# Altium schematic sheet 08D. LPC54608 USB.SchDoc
size A4; CheckedBy: 赵金生; Author: 伍伟业; CompanyName: 广州周立功单片机科技有限公司; DocumentNumber: 11; SheetNumber: 8D; SheetTotal: 19; PageSetup: Record=PageOptions|CenterHorizontal=True|CenterVertical=True|PrintScale=1.00|XCorrection=1.00|YCorrection=1.00|PrintKind=0|BorderSize=5000000|LeftOffset=0|BottomOffset=0|Orientation=2|PaperLength=1000|PaperWidth=1000|Scale=100|PaperSource=7|PrintQuality=600|MediaType=1|DitherType=10|PaperKind=A4|PrintScaleMode=1; DesignDate: 2017-3-16; CheckDate: 2017-3-16; SheetName: LPC54608 USB; SheetVersion: V1.00; SheetDescription: LPC54608的USB总线
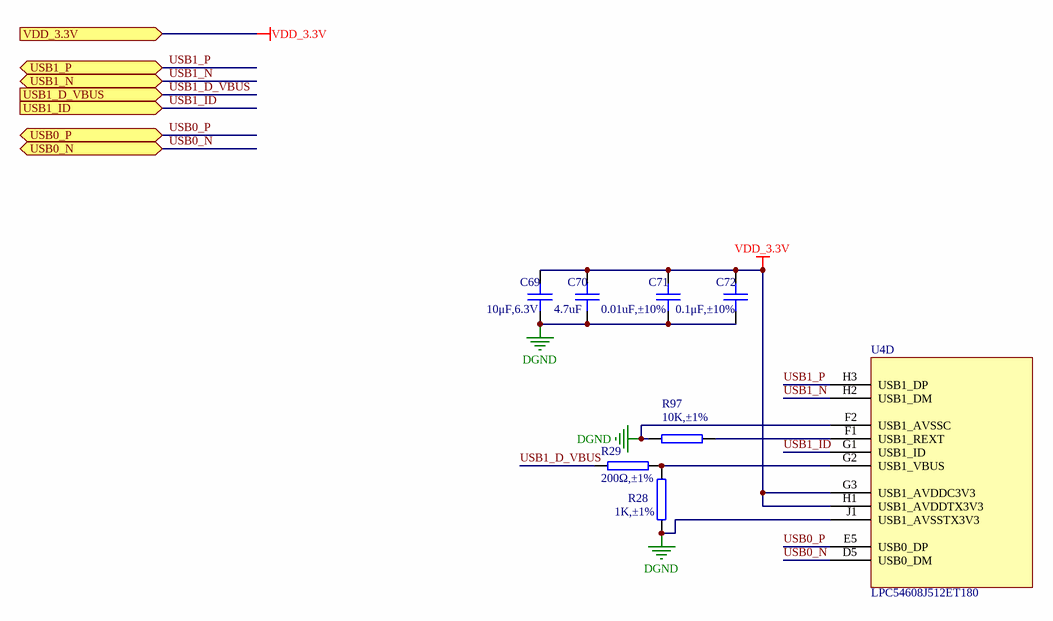
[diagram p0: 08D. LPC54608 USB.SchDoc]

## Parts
C69  10μF,6.3V  [0603C]
C70  4.7uF  [0603C]
C71  0.01uF,±10%  [0402C]
C72  0.1μF,±10%  [0402C]
R28  1K,±1%  [0402R]
R29  200Ω,±1%  [0402R]
R97  10K,±1%  [0402R]
U4  LPC54608J512ET180  [BGA180C80P14x14]  (part D of 5)

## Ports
USB0_N (bidir), USB0_P (bidir), USB1_D_VBUS (in), USB1_ID (in), USB1_N (bidir), USB1_P (bidir), VDD_3.3V (in)

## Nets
DGND: C69.2 C70.2 C71.2 C72.2 R28.2 R97.1 U4.F2(USB1_AVSSC) U4.J1(USB1_AVSSTX3V3)
VDD_3.3V: C69.1 C70.1 C71.1 C72.1 U4.G3(USB1_AVDDC3V3) U4.H1(USB1_AVDDTX3V3) ; port VDD_3.3V
USB0_N: U4.D5(USB0_DM) ; port USB0_N
USB0_P: U4.E5(USB0_DP) ; port USB0_P
USB1_D_VBUS: R29.2 ; port USB1_D_VBUS
USB1_ID: U4.G1(USB1_ID) ; port USB1_ID
USB1_N: U4.H2(USB1_DM) ; port USB1_N
USB1_P: U4.H3(USB1_DP) ; port USB1_P
NetR28_1: R28.1 R29.1 U4.G2(USB1_VBUS)
NetR97_2: R97.2 U4.F1(USB1_REXT)

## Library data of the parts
C69 = 1.02.01.0065: 10μF,6.3V,X5R,GRM188R60J106M****,0603,Murata,RoHS; 名称: 电容; 封装: 0603; 贴片和直插: SMT; 器件优选方案: 正常状态，可以选用
C70 = 1.02.01.0080: GRM188R61A475KE15D,4.7uF,±10%,10V,X5R,0603,muRata,RoHS; 名称: 电容; 封装: 0603; 贴片和直插: SMT; PCB备注: 160602yjh; 器件优选方案: 正常状态，可以选用
C71 = 1.02.17.0019: GRM155R71H103KA88D,0.01uF,±10%,50V,X7R,0402,muRata,RoHS; 名称: 电容; 封装: 0402; 设备封装名称: C0402_0.01uF_X7R_50V_10%; 贴片和直插: SMT; 器件优选方案: 正常状态，可以选用
C72 = 1.02.17.0006: GRM155R71C104KA88D,0.1μF,±10%,16V,X7R,0402,muRata,RoHS; 名称: 电容; 封装: 0402; 设备封装名称: C0402_0.1uF_X7R_16V_10%; 贴片和直插: SMT; 器件优选方案: 正常状态，可以选用
R28 = 1.01.17.0016: 1K,±1%,0402,RALEC,RoHS; 名称: 电阻; 封装: 0402; 设备封装名称: R0402_1K_1%; 贴片和直插: SMT; 器件优选方案: 正常状态，可以选用
R29 = 1.01.17.0073: 200Ω,±1%,0402,RoHS; 名称: 电阻; 封装: 0402; 设备封装名称: R0402_200R_1%; 厂商: Ralec; 贴片和直插: SMT; 器件优选方案: 正常状态，可以选用
R97 = 1.01.17.0034: 10K,±1%,0402,RALEC,RoHS; 名称: 电阻; 封装: 0402; 设备封装名称: R0402_10K_1%; 贴片和直插: SMT; 器件优选方案: 正常状态，可以选用
U4 = 1.05.02.0192: LPC54608J512ET180,TFBGA180,NXP,RoHS; 名称: 集成电路(临时); 贴片和直插: SMT; PCB备注: 170314lmd; 器件优选方案: 临时/偏门物料/不主推物料，谨慎选用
